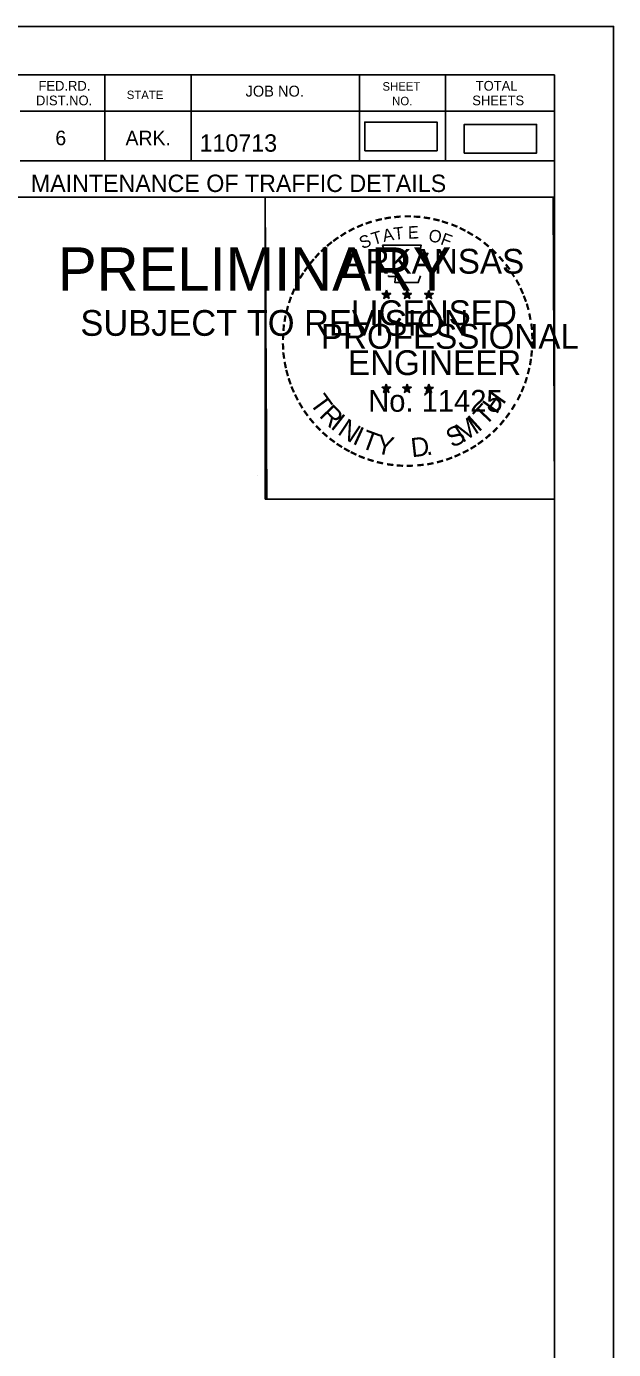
# Model space of a CAD drawing. Extents: x 1678017 to 1687792, y 404433 to 413488.
# Drawn here: x 1681039 to 1681275, y 404967 to 405500 of the extents above; entities that cross this region are included whole.
import ezdxf

# ---------------------------------------------------------------- set-up
doc = ezdxf.new("R2010")
doc.units = 0
for name, color, linetype in [('Default', 7, 'Continuous'), ('S_BUILDING', 7, 'Continuous'), ('S_GATE', 7, 'Continuous'), ('S_STREAM', 7, 'Continuous'), ('S_UNDERGROUND_CABLE', 7, 'Continuous')]:
    doc.layers.add(name, color=color, linetype=linetype)

msp = doc.modelspace()

# ---------------------------------------------------------------- linework, layer by layer
at = {"layer": 'Default'}
for points in [[(1681174.99, 405449.73), (1681204.15, 405449.73), (1681204.15, 405461.28), (1681174.99, 405461.28)], [(1681215.06, 405448.81), (1681244.23, 405448.81), (1681244.23, 405460.36), (1681215.06, 405460.36)]]:
    msp.add_lwpolyline(points, close=True, dxfattribs=at)
at = {"layer": 'S_BUILDING'}
for p, q in [((1679670.61, 405480.38), (1681251.51, 405480.38)), ((1681070.21, 405480.38), (1681070.21, 405445.68)), ((1681104.91, 405480.38), (1681104.91, 405445.68)), ((1681172.81, 405480.38), (1681172.81, 405445.68)), ((1681207.51, 405480.38), (1681207.51, 405445.68)), ((1681251.51, 404453.08), (1681251.51, 405480.38)), ((1681251.51, 405465.68), (1681036.01, 405465.68)), ((1681251.51, 405465.78), (1681251.51, 405465.78)), ((1681251.51, 405445.68), (1681036.01, 405445.68)), ((1681050.81, 405445.68), (1681251.51, 405445.68)), ((1681251.51, 405430.98), (1680938.31, 405430.98))]:
    msp.add_line(p, q, dxfattribs=at)
at = {"layer": 'S_GATE'}
for p, q in [((1681181.94, 405392.26), (1681183.68, 405391.7)), ((1681181.94, 405392.26), (1681183.2, 405392.03)), ((1681181.94, 405392.26), (1681183.12, 405391.65)), ((1681182.6, 405390.22), (1681183.68, 405391.7)), ((1681182.6, 405390.22), (1681183.23, 405391.44)), ((1681182.6, 405390.22), (1681183.67, 405391.3)), ((1681183.68, 405393.53), (1681183.48, 405392.27)), ((1681184.75, 405390.22), (1681183.67, 405391.29)), ((1681183.68, 405391.7), (1681183.68, 405393.53)), ((1681183.68, 405393.53), (1681183.93, 405392.28)), ((1681185.42, 405392.26), (1681183.68, 405391.7)), ((1681184.75, 405390.22), (1681183.68, 405391.7)), ((1681185.42, 405392.26), (1681183.99, 405392.01)), ((1681184.75, 405390.22), (1681184.06, 405391.67)), ((1681185.42, 405392.26), (1681184.4, 405391.75)), ((1681190.29, 405392.26), (1681192.03, 405391.7)), ((1681190.29, 405392.26), (1681191.55, 405392.03)), ((1681190.29, 405392.26), (1681191.47, 405391.65)), ((1681190.95, 405390.22), (1681192.03, 405391.7)), ((1681190.95, 405390.22), (1681191.58, 405391.44)), ((1681190.95, 405390.22), (1681192.02, 405391.3)), ((1681192.03, 405393.53), (1681191.83, 405392.27)), ((1681193.1, 405390.22), (1681192.02, 405391.29)), ((1681192.03, 405391.7), (1681192.03, 405393.53)), ((1681192.03, 405393.53), (1681192.28, 405392.28)), ((1681193.77, 405392.26), (1681192.03, 405391.7)), ((1681193.1, 405390.22), (1681192.03, 405391.7)), ((1681193.77, 405392.26), (1681192.34, 405392.01)), ((1681193.1, 405390.22), (1681192.41, 405391.67)), ((1681193.77, 405392.26), (1681192.75, 405391.75)), ((1681199.11, 405392.2), (1681200.85, 405391.64)), ((1681199.11, 405392.2), (1681200.37, 405391.97)), ((1681199.11, 405392.2), (1681200.29, 405391.59)), ((1681199.77, 405390.16), (1681200.85, 405391.64)), ((1681199.77, 405390.16), (1681200.4, 405391.38)), ((1681199.77, 405390.16), (1681200.84, 405391.24)), ((1681200.85, 405393.47), (1681200.65, 405392.21)), ((1681201.92, 405390.16), (1681200.84, 405391.23)), ((1681200.85, 405391.64), (1681200.85, 405393.47)), ((1681200.85, 405393.47), (1681201.1, 405392.22)), ((1681202.59, 405392.2), (1681200.85, 405391.64)), ((1681201.92, 405390.16), (1681200.85, 405391.64)), ((1681202.59, 405392.2), (1681201.16, 405391.95)), ((1681201.92, 405390.16), (1681201.23, 405391.61)), ((1681202.59, 405392.2), (1681201.57, 405391.69)), ((1681181.92, 405354.39), (1681183.66, 405353.84)), ((1681181.92, 405354.39), (1681183.18, 405354.17)), ((1681181.92, 405354.39), (1681183.1, 405353.78)), ((1681182.58, 405352.35), (1681183.66, 405353.84)), ((1681182.58, 405352.35), (1681183.21, 405353.57)), ((1681182.58, 405352.35), (1681183.65, 405353.44)), ((1681183.66, 405355.66), (1681183.46, 405354.4)), ((1681184.73, 405352.35), (1681183.65, 405353.42)), ((1681183.66, 405353.84), (1681183.66, 405355.66)), ((1681183.66, 405355.66), (1681183.91, 405354.41)), ((1681185.4, 405354.39), (1681183.66, 405353.84)), ((1681184.73, 405352.35), (1681183.66, 405353.84)), ((1681185.4, 405354.39), (1681183.97, 405354.15)), ((1681184.73, 405352.35), (1681184.04, 405353.81)), ((1681185.4, 405354.39), (1681184.38, 405353.88)), ((1681190.26, 405354.39), (1681192.01, 405353.84)), ((1681190.26, 405354.39), (1681191.53, 405354.17)), ((1681190.26, 405354.39), (1681191.45, 405353.78)), ((1681190.93, 405352.35), (1681192.01, 405353.84)), ((1681190.93, 405352.35), (1681191.56, 405353.57)), ((1681190.93, 405352.35), (1681192, 405353.44)), ((1681192.01, 405355.66), (1681191.8, 405354.4)), ((1681193.07, 405352.35), (1681192, 405353.42)), ((1681192.01, 405353.84), (1681192.01, 405355.66)), ((1681192.01, 405355.66), (1681192.25, 405354.41)), ((1681193.74, 405354.39), (1681192.01, 405353.84)), ((1681193.07, 405352.35), (1681192.01, 405353.84)), ((1681193.74, 405354.39), (1681192.31, 405354.15)), ((1681193.07, 405352.35), (1681192.39, 405353.81)), ((1681193.74, 405354.39), (1681192.72, 405353.88)), ((1681199.1, 405354.34), (1681200.84, 405353.79)), ((1681199.1, 405354.34), (1681200.36, 405354.12)), ((1681199.1, 405354.34), (1681200.28, 405353.73)), ((1681199.76, 405352.3), (1681200.84, 405353.79)), ((1681199.76, 405352.3), (1681200.39, 405353.52)), ((1681199.76, 405352.3), (1681200.83, 405353.39)), ((1681200.84, 405355.61), (1681200.64, 405354.35)), ((1681201.91, 405352.3), (1681200.83, 405353.37)), ((1681200.84, 405353.79), (1681200.84, 405355.61)), ((1681200.84, 405355.61), (1681201.09, 405354.36)), ((1681202.58, 405354.34), (1681200.84, 405353.79)), ((1681201.91, 405352.3), (1681200.84, 405353.79)), ((1681202.58, 405354.34), (1681201.15, 405354.1)), ((1681201.91, 405352.3), (1681201.22, 405353.76)), ((1681202.58, 405354.34), (1681201.56, 405353.83))]:
    msp.add_line(p, q, dxfattribs=at)
for points in [[(1681182.14, 405411.65), (1681183.49, 405407.51)], [(1681199.7, 405407.04), (1681200.41, 405408.46), (1681196.98, 405408.34), (1681197.72, 405411.65), (1681182.14, 405411.65)], [(1681184.6, 405399.53), (1681184.6, 405399.1), (1681187.42, 405399), (1681187.15, 405396.64), (1681196.5, 405396.64), (1681197.5, 405399.32)], [(1681183.68, 405393.53), (1681184.75, 405390.22), (1681181.94, 405392.26), (1681185.42, 405392.26), (1681182.6, 405390.22), (1681183.68, 405393.53)], [(1681192.03, 405393.53), (1681193.1, 405390.22), (1681190.29, 405392.26), (1681193.77, 405392.26), (1681190.95, 405390.22), (1681192.03, 405393.53)], [(1681200.85, 405393.47), (1681201.92, 405390.16), (1681199.11, 405392.2), (1681202.59, 405392.2), (1681199.77, 405390.16), (1681200.85, 405393.47)], [(1681183.66, 405355.66), (1681184.73, 405352.35), (1681181.92, 405354.39), (1681185.4, 405354.39), (1681182.58, 405352.35), (1681183.66, 405355.66)], [(1681192.01, 405355.66), (1681193.07, 405352.35), (1681190.26, 405354.39), (1681193.74, 405354.39), (1681190.93, 405352.35), (1681192.01, 405355.66)], [(1681200.84, 405355.61), (1681201.91, 405352.3), (1681199.1, 405354.34), (1681202.58, 405354.34), (1681199.76, 405352.3), (1681200.84, 405355.61)]]:
    msp.add_lwpolyline(points, dxfattribs=at)
for centre, radius in [((1681183.68, 405391.7), 0.861), ((1681183.68, 405391.7), 0.723), ((1681183.68, 405391.7), 0.579), ((1681183.68, 405391.7), 0.495), ((1681183.68, 405391.7), 0.374), ((1681183.68, 405391.7), 0.248), ((1681183.68, 405391.7), 0.148), ((1681192.03, 405391.7), 0.861), ((1681192.03, 405391.7), 0.723), ((1681192.03, 405391.7), 0.579), ((1681192.03, 405391.7), 0.495), ((1681192.03, 405391.7), 0.374), ((1681192.03, 405391.7), 0.248), ((1681192.03, 405391.7), 0.148), ((1681200.85, 405391.64), 0.861), ((1681200.85, 405391.64), 0.723), ((1681200.85, 405391.64), 0.579), ((1681200.85, 405391.64), 0.495), ((1681200.85, 405391.64), 0.374), ((1681200.85, 405391.64), 0.248), ((1681200.85, 405391.64), 0.148), ((1681183.66, 405353.83), 0.861), ((1681183.66, 405353.83), 0.723), ((1681183.66, 405353.83), 0.579), ((1681183.66, 405353.83), 0.495), ((1681183.66, 405353.83), 0.374), ((1681183.66, 405353.83), 0.248), ((1681183.66, 405353.83), 0.148), ((1681192, 405353.83), 0.861), ((1681192, 405353.83), 0.723), ((1681192, 405353.83), 0.579), ((1681192, 405353.83), 0.495), ((1681192, 405353.83), 0.374), ((1681192, 405353.83), 0.248), ((1681192, 405353.83), 0.148), ((1681200.84, 405353.78), 0.861), ((1681200.84, 405353.78), 0.723), ((1681200.84, 405353.78), 0.579), ((1681200.84, 405353.78), 0.495), ((1681200.84, 405353.78), 0.374), ((1681200.84, 405353.78), 0.248), ((1681200.84, 405353.78), 0.148)]:
    msp.add_circle(centre, radius, dxfattribs=at)
at = {"layer": 'S_STREAM'}
for p, q in [((1679608.61, 405499.86), (1681275.28, 405499.86)), ((1681131.69, 405318.7), (1681131.69, 405318.7))]:
    msp.add_line(p, q, dxfattribs=at)
for points in [[(1679608.58, 405499.86), (1681275.28, 405499.86), (1681275.28, 404433.17), (1679608.58, 404433.17)], [(1680840.21, 405480.38), (1680938.31, 405480.38), (1680938.31, 405430.98), (1681018.87, 405430.98), (1681134.87, 405430.98), (1681134.87, 405309.32), (1681251.51, 405309.32), (1681251.51, 404453.08), (1679670.61, 404453.08), (1679670.61, 405480.38)], [(1681134.87, 405430.98), (1681250.91, 405430.98), (1681251.51, 405309.32), (1681135.47, 405309.32)]]:
    msp.add_lwpolyline(points, close=True, dxfattribs=at)

# ---------------------------------------------------------------- texts
at = {"layer": 'S_BUILDING'}
for s, height, p in [('FED.RD.', 3.91, (1681043.41, 405473.98)), ('JOB NO.', 4.396, (1681126.91, 405471.58)), ('SHEET', 3.42, (1681182.11, 405473.98)), ('TOTAL', 3.91, (1681219.71, 405473.98)), ('DIST.NO.', 3.91, (1681042.41, 405468.08)), ('STATE', 3.42, (1681079.01, 405470.58)), ('NO.', 3.42, (1681186.01, 405468.08)), ('SHEETS', 3.91, (1681218.31, 405468.08)), ('6', 5.86, (1681050.21, 405451.98)), ('ARK.', 5.861, (1681078.51, 405451.98)), ('110713', 7, (1681108.39, 405449.38)), ('MAINTENANCE OF TRAFFIC DETAILS', 7, (1681040.33, 405433.13))]:
    msp.add_text(s, height=height, dxfattribs=at).set_placement(p)
at = {"layer": 'S_GATE'}
for s, height, rotation, p in [('-', 8, 19.1761, (1681175.88, 405417.28)), ('-', 8, 13.6302, (1681179.63, 405418.49)), ('-', 8, 10.2193, (1681183.02, 405419.3)), ('-', 8, 5.8968, (1681186.67, 405419.85)), ('-', 8, 0.1862, (1681190.53, 405420.21)), ('-', 8, 357.743, (1681194.14, 405420.14)), ('-', 8, 352.1617, (1681197.86, 405419.86)), ('-', 8, 347.2049, (1681201.46, 405419.29)), ('-', 8, 342.3362, (1681204.63, 405418.52)), ('-', 8, 34.0636, (1681166.56, 405412.5)), ('-', 8, 28.7918, (1681169.55, 405414.35)), ('-', 8, 24.3072, (1681172.71, 405415.94)), ('T', 5, 16.4036, (1681178.49, 405411.69)), ('A', 5, 11.2132, (1681182.62, 405412.95)), ('T', 5, 6.0228, (1681186.86, 405413.78)), ('E', 5, 0.8323, (1681192.39, 405414.33)), ('O', 5, 350.4515, (1681200.41, 405413.28)), ('F', 5, 340.0707, (1681205.18, 405412.14)), ('-', 8, 337.8551, (1681208.31, 405417.4)), ('-', 8, 334.1211, (1681211.46, 405416.05)), ('-', 8, 329.6409, (1681214.36, 405414.63)), ('-', 8, 42.9622, (1681159.13, 405406.55)), ('-', 8, 38.9507, (1681161.29, 405408.64)), ('-', 8, 36.2317, (1681163.67, 405410.53)), ('S', 5, 21.594, (1681173.92, 405410.04)), ('-', 8, 325.8627, (1681217.57, 405412.83)), ('-', 8, 320.5297, (1681220.62, 405410.7)), ('-', 8, 50.6142, (1681154.87, 405401.73)), ('-', 8, 48.4231, (1681156.89, 405404.16)), ('-', 8, 315.5786, (1681223.62, 405408.26)), ('-', 8, 309.8797, (1681226.46, 405405.51)), ('-', 8, 58.0706, (1681151.18, 405396.26)), ('-', 8, 54.2325, (1681152.81, 405398.9)), ('-', 8, 306.6522, (1681229.09, 405402.5)), ('-', 7, 303.6753, (1681231.52, 405399.66)), ('-', 8, 62.8713, (1681149.62, 405393.19)), ('-', 8, 299.6684, (1681233.11, 405396.62)), ('-', 8, 72.3945, (1681147.23, 405386.99)), ('-', 8, 67.7743, (1681148.32, 405390.14)), ('-', 8, 294.6628, (1681234.73, 405393.56)), ('-', 8, 290.5728, (1681236.02, 405390.68)), ('-', 8, 75.461, (1681146.24, 405383.42)), ('-', 8, 285.1233, (1681237.19, 405387.78)), ('-', 8, 280.5493, (1681238.19, 405384.07)), ('-', 8, 85.1863, (1681145.2, 405376.4)), ('-', 8, 81.2013, (1681145.58, 405379.85)), ('-', 8, 276.5962, (1681239, 405380.23)), ('-', 8, 89.0622, (1681145.08, 405372.89)), ('-', 8, 274.3301, (1681239.3, 405376.62)), ('-', 8, 94.1959, (1681145.25, 405369.27)), ('-', 8, 98.9479, (1681145.61, 405365.93)), ('-', 8, 263.5172, (1681239.37, 405370.13)), ('-', 8, 269.9407, (1681239.47, 405373.46)), ('-', 8, 101.7149, (1681146.29, 405362.27)), ('-', 8, 260.9953, (1681239.02, 405366.86)), ('-', 8, 105.4578, (1681147.1, 405359.29)), ('-', 8, 109.0874, (1681148.17, 405356.14)), ('-', 8, 252.8681, (1681237.56, 405359.87)), ('-', 8, 255.7626, (1681238.47, 405363.47)), ('-', 8, 114.0643, (1681149.44, 405353.16)), ('T', 7.7, 306.0406, (1681152.46, 405348.03)), ('H', 7.7, 54.6088, (1681228.06, 405343.2)), ('-', 8, 247.8887, (1681236.45, 405356.5)), ('-', 8, 115.7289, (1681150.97, 405350.07)), ('-', 8, 120.4471, (1681152.75, 405347.14)), ('R', 7.7, 314.005, (1681156.27, 405342.79)), ('T', 7.7, 46.6444, (1681223.61, 405338.49)), ('-', 8, 239.0712, (1681233.17, 405349.6)), ('-', 8, 244.6197, (1681235.14, 405353.36)), ('-', 8, 125.8934, (1681154.77, 405344.33)), ('-', 8, 130.7181, (1681157.08, 405341.57)), ('I', 7.7, 321.9694, (1681160.78, 405338.13)), ('N', 7.7, 326.5002, (1681163.61, 405335.77)), ('M', 7.7, 32.6563, (1681214.39, 405331.87)), ('I', 7.7, 42.1136, (1681220.81, 405336.1)), ('-', 8, 231.2538, (1681229.01, 405343.5)), ('-', 8, 233.8452, (1681231.16, 405346.33)), ('-', 8, 134.2238, (1681159.66, 405338.85)), ('-', 8, 138.9338, (1681162.29, 405336.53)), ('I', 7.7, 335.3603, (1681169.65, 405331.84)), ('T', 7.7, 339.8912, (1681172.96, 405330.2)), ('S', 7.7, 26.9312, (1681210.19, 405329.84)), ('-', 8, 225.7653, (1681226.61, 405340.68)), ('-', 8, 144.6463, (1681165.07, 405334.5)), ('-', 8, 148.0898, (1681167.87, 405332.64)), ('Y', 7.7, 347.8556, (1681179.04, 405327.98)), ('D', 7.7, 6.3969, (1681193.97, 405326.18)), ('-', 8, 212.2491, (1681218.59, 405333.84)), ('-', 8, 215.7363, (1681221.26, 405335.78)), ('-', 8, 221.0851, (1681224, 405338.14)), ('-', 8, 151.5704, (1681170.77, 405331.02)), ('-', 8, 154.6002, (1681173.38, 405329.78)), ('-', 8, 158.5612, (1681176.5, 405328.51)), ('-', 8, 162.7983, (1681179.93, 405327.45)), ('.', 7.7, 13.7642, (1681199.93, 405326.82)), ('-', 8, 200.7184, (1681209.58, 405329.15)), ('-', 8, 204.2516, (1681212.68, 405330.52)), ('-', 8, 207.3568, (1681215.8, 405332.11)), ('-', 8, 167.5555, (1681183.51, 405326.63)), ('-', 8, 173.1155, (1681187.37, 405326.08)), ('-', 8, 176.5183, (1681191.11, 405325.81)), ('-', 8, 181.5918, (1681194.83, 405325.91)), ('-', 8, 185.8167, (1681198.87, 405326.29)), ('-', 8, 191.2858, (1681202.55, 405326.95)), ('-', 8, 195.4743, (1681206.2, 405327.94))]:
    msp.add_text(s, height=height, rotation=rotation, dxfattribs=at).set_placement(p)
for s, height, p in [('ARKANSAS', 10, (1681166.41, 405400.21)), ('LICENSED', 10, (1681169.4, 405379.46)), ('DWB', 0.05, (1681183.62, 405391.68)), ('DWB', 0.05, (1681191.97, 405391.68)), ('DWB', 0.05, (1681200.79, 405391.62)), ('PROFESSIONAL', 10, (1681157.28, 405369.94)), ('ENGINEER', 10, (1681168.21, 405359.32)), ('No. 11425', 8.785, (1681176.35, 405344.56)), ('DWB', 0.05, (1681183.6, 405353.81)), ('DWB', 0.05, (1681191.94, 405353.81)), ('DWB', 0.05, (1681200.78, 405353.76))]:
    msp.add_text(s, height=height, dxfattribs=at).set_placement(p)
at = {"layer": 'S_UNDERGROUND_CABLE'}
for s, height, p in [('PRELIMINARY', 17.5, (1681051.27, 405393.3)), ('DWB', 0.05, (1681055, 405402.54)), ('SUBJECT TO REVISION', 10.3756, (1681060.31, 405375.15))]:
    msp.add_text(s, height=height, dxfattribs=at).set_placement(p)

doc.saveas('drawing.dxf')
